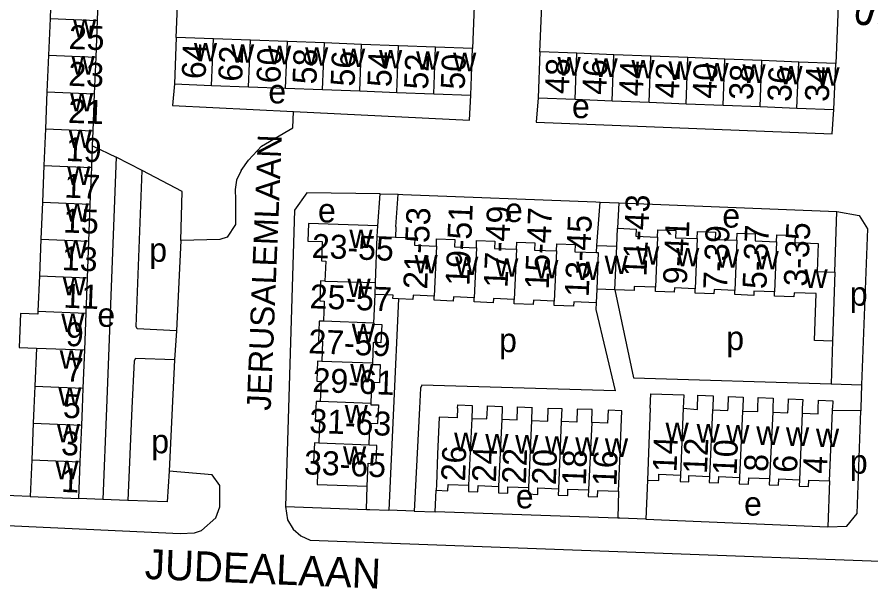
# Model space of a CAD drawing. Extents: x 159675 to 162108, y 386471 to 388472.
# Drawn here: x 161483.1 to 161625.6, y 387220.7 to 387315.3 of the extents above; entities that cross this region are included whole.
import ezdxf

# ---------------------------------------------------------------- set-up
doc = ezdxf.new("R2010")
doc.units = 0
for name, color, linetype in [('BLT_Basislijn', 7, 'Continuous'), ('BLT_Bebouwing', 7, 'Continuous'), ('BLT_Centroide', 7, 'Continuous'), ('BLT_Huisnummer', 7, 'Continuous'), ('BLT_Huisnummer_ tussenligend', 7, 'Continuous'), ('BLT_Huisnummer_reeks', 7, 'Continuous'), ('BLT_Onderdoorgang_en_onderverdeling', 7, 'Continuous'), ('BLT_Onderverdeling_panden', 7, 'Continuous'), ('BLT_Straatnaam', 7, 'Continuous'), ('BLT_Straatnaam_verkleind', 7, 'Continuous')]:
    doc.layers.add(name, color=color, linetype=linetype)

msp = doc.modelspace()

# ---------------------------------------------------------------- linework, layer by layer
at = {"layer": 'BLT_Basislijn'}
for p, q in [((161509.67, 387311.89), (161510.15, 387324.8)), ((161559.58, 387322.6), (161559.09, 387310.04)), ((161570.35, 387309.51), (161570.84, 387322.24)), ((161620.23, 387320.2), (161619.72, 387307.54)), ((161495.7, 387293.78), (161499.65, 387291.89)), ((161499.65, 387291.89), (161498.02, 387250)), ((161503.99, 387289.7), (161499.65, 387291.89)), ((161543.27, 387280.42), (161543.71, 387285.81)), ((161543.71, 387285.81), (161546.67, 387285.72)), ((161546.3, 387280.3), (161546.67, 387285.72)), ((161579.85, 387277.18), (161580.4, 387284.4)), ((161580.4, 387284.4), (161583.52, 387284.28)), ((161583.52, 387284.28), (161583.29, 387280.03)), ((161583.52, 387284.28), (161619.87, 387282.84)), ((161619.54, 387272.72), (161619.87, 387282.84)), ((161546.3, 387280.3), (161546.23, 387278.55)), ((161510.45, 387278.01), (161509.72, 387262.95)), ((161546.72, 387268.27), (161545.9, 387250)), ((161509.72, 387262.95), (161509.39, 387258.09)), ((161619.17, 387261.21), (161618.94, 387254.08)), ((161509.39, 387258.09), (161508.99, 387250)), ((161618.94, 387254.08), (161624.01, 387253.93)), ((161624.01, 387253.93), (161623.89, 387250)), ((161498.02, 387250), (161497.42, 387234.78)), ((161502.27, 387250), (161501.56, 387234.62)), ((161508.99, 387250), (161508.47, 387239.5)), ((161528.41, 387250), (161527.91, 387233.59)), ((161545.9, 387250), (161545.13, 387232.97)), ((161550.26, 387250), (161549.36, 387232.83)), ((161623.88, 387249.57), (161619.14, 387249.65)), ((161623.89, 387250), (161623.88, 387249.57)), ((161588.29, 387238.02), (161588.03, 387231.49)), ((161618.68, 387237.87), (161618.37, 387230.19)), ((161541.43, 387233.1), (161541.54, 387236.98)), ((161552.86, 387232.71), (161553.02, 387236.32)), ((161485.3, 387235.26), (161473.27, 387235.78)), ((161497.42, 387234.78), (161493.41, 387234.93)), ((161583.47, 387236.17), (161583.37, 387231.68)), ((161501.56, 387234.62), (161497.42, 387234.78)), ((161527.91, 387233.59), (161541.43, 387233.1)), ((161549.36, 387232.83), (161545.13, 387232.97)), ((161549.36, 387232.83), (161552.86, 387232.71)), ((161583.37, 387231.68), (161552.86, 387232.71)), ((161588.03, 387231.49), (161618.37, 387230.19))]:
    msp.add_line(p, q, dxfattribs=at)
for points in [[(161509.38, 387304.12), (161509.03, 387300.52), (161529.2, 387299.52)], [(161529.2, 387299.52), (161558.61, 387298.06), (161558.8, 387302.25)], [(161570.05, 387301.81), (161569.73, 387297.74), (161619.1, 387295.81), (161619.41, 387299.85)], [(161520.47, 387289.7), (161521.73, 387291.4), (161523.89, 387293.76), (161529.09, 387296.81), (161529.2, 387299.52)], [(161509.72, 387262.95), (161503.12, 387263.25), (161502.99, 387263.62), (161503.99, 387289.7)], [(161510.45, 387278.01), (161510.64, 387286.16), (161503.99, 387289.7)], [(161520.47, 387289.7), (161519.69, 387288.07), (161519.49, 387286.51), (161519.52, 387284.82), (161519.57, 387280.69), (161518.14, 387278.53), (161516.96, 387278.16), (161510.45, 387278.01)], [(161543.71, 387285.81), (161531.44, 387285.94), (161529.41, 387283.05), (161528.41, 387250)], [(161546.67, 387285.72), (161547.47, 387285.69), (161579.65, 387284.43), (161580.4, 387284.4)], [(161619.87, 387282.84), (161623.59, 387282.17), (161624.99, 387279.93), (161624.01, 387253.93)], [(161582.86, 387269.76), (161585.96, 387255.09), (161618.94, 387254.08)], [(161579.73, 387267.58), (161579.68, 387266.5), (161582.9, 387252.91), (161550.66, 387253.83), (161550.43, 387253.33), (161550.26, 387250)], [(161509.39, 387258.09), (161502.88, 387258.29), (161502.64, 387257.94), (161502.27, 387250)], [(161618.37, 387230.19), (161621.57, 387230.31), (161623.29, 387232.41), (161623.88, 387249.57)], [(161423.81, 387236.03), (161425.85, 387233.74), (161426.74, 387233.29), (161429.71, 387232.82), (161510.3, 387229.1), (161512.68, 387229.19), (161513.9, 387229.58), (161516.29, 387231.74), (161516.94, 387233.55), (161516.96, 387237.09), (161515.67, 387238.87), (161508.47, 387239.5)], [(161508.47, 387239.5), (161508.16, 387234.37), (161501.56, 387234.62)], [(161527.91, 387233.59), (161528.24, 387231.4), (161529.19, 387229.84), (161530.47, 387228.72), (161532.02, 387228.01), (161634.68, 387224.19), (161640.03, 387222.45), (161643.68, 387219.17), (161645.58, 387219.17)], [(161541.43, 387233.1), (161541.94, 387233.08), (161545.13, 387232.97)], [(161588.03, 387231.49), (161583.68, 387231.67), (161583.37, 387231.68)]]:
    msp.add_lwpolyline(points, dxfattribs=at)
at = {"layer": 'BLT_Bebouwing'}
for p, q in [((161488.85, 387321.21), (161488.6, 387315.07)), ((161488.6, 387315.07), (161488.34, 387308.93)), ((161496.28, 387308.6), (161496.51, 387314.74)), ((161509.67, 387311.89), (161509.38, 387304.12)), ((161515.85, 387311.66), (161509.67, 387311.89)), ((161522.03, 387311.43), (161515.85, 387311.66)), ((161528.21, 387311.2), (161522.03, 387311.43)), ((161534.39, 387310.96), (161528.21, 387311.2)), ((161540.56, 387310.73), (161534.39, 387310.96)), ((161546.74, 387310.5), (161540.56, 387310.73)), ((161552.92, 387310.27), (161546.74, 387310.5)), ((161559.09, 387310.04), (161552.92, 387310.27)), ((161558.8, 387302.25), (161559.09, 387310.04)), ((161570.35, 387309.51), (161570.05, 387301.81)), ((161576.52, 387309.26), (161570.35, 387309.51)), ((161582.7, 387309.01), (161576.52, 387309.26)), ((161588.87, 387308.77), (161582.7, 387309.01)), ((161488.34, 387308.93), (161488.09, 387302.79)), ((161496.04, 387302.46), (161496.28, 387308.6)), ((161595.04, 387308.52), (161588.87, 387308.77)), ((161601.21, 387308.28), (161595.04, 387308.52)), ((161607.38, 387308.03), (161601.21, 387308.28)), ((161613.55, 387307.78), (161607.38, 387308.03)), ((161619.72, 387307.54), (161613.55, 387307.78)), ((161619.41, 387299.85), (161619.72, 387307.54)), ((161509.38, 387304.12), (161515.56, 387303.88)), ((161515.56, 387303.88), (161521.74, 387303.65)), ((161521.74, 387303.65), (161527.91, 387303.42)), ((161527.91, 387303.42), (161534.09, 387303.18)), ((161488.09, 387302.79), (161487.84, 387296.65)), ((161495.8, 387296.32), (161496.04, 387302.46)), ((161534.09, 387303.18), (161540.27, 387302.95)), ((161540.27, 387302.95), (161546.45, 387302.71)), ((161546.45, 387302.71), (161552.62, 387302.48)), ((161552.62, 387302.48), (161558.8, 387302.25)), ((161570.05, 387301.81), (161576.22, 387301.57)), ((161576.22, 387301.57), (161582.39, 387301.32)), ((161582.39, 387301.32), (161588.56, 387301.08)), ((161588.56, 387301.08), (161594.73, 387300.83)), ((161594.73, 387300.83), (161600.9, 387300.58)), ((161600.9, 387300.58), (161607.07, 387300.34)), ((161607.07, 387300.34), (161613.24, 387300.09)), ((161613.24, 387300.09), (161619.41, 387299.85)), ((161487.84, 387296.65), (161487.58, 387290.51)), ((161495.7, 387293.78), (161495.8, 387296.32)), ((161495.56, 387290.18), (161495.7, 387293.78)), ((161487.58, 387290.51), (161487.33, 387284.37)), ((161495.32, 387284.04), (161495.56, 387290.18)), ((161487.33, 387284.37), (161487.07, 387278.23)), ((161495.08, 387277.9), (161495.32, 387284.04)), ((161543.2, 387278.66), (161543.27, 387280.42)), ((161487.07, 387278.23), (161486.82, 387272.09)), ((161494.84, 387271.76), (161495.08, 387277.9)), ((161543.2, 387278.66), (161546.23, 387278.55)), ((161579.8, 387275.98), (161579.85, 387277.18)), ((161579.85, 387277.18), (161583.17, 387277.05)), ((161486.82, 387272.09), (161486.58, 387266.2)), ((161619.54, 387272.72), (161619.17, 387261.21)), ((161494.62, 387265.89), (161494.84, 387271.76)), ((161579.82, 387269.88), (161579.73, 387267.58)), ((161582.86, 387269.76), (161579.82, 387269.88)), ((161542.64, 387264.21), (161542.83, 387268.97)), ((161494.38, 387259.74), (161494.62, 387265.89)), ((161486.32, 387260.05), (161486.06, 387253.68)), ((161494.13, 387253.34), (161494.38, 387259.74)), ((161486.06, 387253.68), (161485.91, 387250)), ((161494, 387250), (161494.13, 387253.34)), ((161485.91, 387250), (161485.81, 387247.54)), ((161493.89, 387247.2), (161494, 387250)), ((161559.02, 387250), (161558.96, 387248.31)), ((161564.06, 387250), (161563.99, 387248.16)), ((161569.02, 387250), (161568.95, 387247.97)), ((161599.18, 387250), (161599.17, 387249.73)), ((161604.18, 387250), (161604.17, 387249.54)), ((161609.22, 387250), (161609.2, 387249.36)), ((161614.13, 387250), (161614.1, 387249.16)), ((161618.68, 387237.87), (161619.14, 387249.65)), ((161619.14, 387249.65), (161619.16, 387250)), ((161485.81, 387247.54), (161485.55, 387241.4)), ((161493.65, 387241.06), (161493.89, 387247.2)), ((161533.44, 387244.18), (161532.71, 387244.21)), ((161485.55, 387241.4), (161485.3, 387235.26)), ((161493.41, 387234.93), (161493.65, 387241.06)), ((161485.3, 387235.26), (161493.41, 387234.93))]:
    msp.add_line(p, q, dxfattribs=at)
for points in [[(161496.51, 387314.74), (161496.7, 387319.6), (161496.91, 387319.59), (161496.96, 387320.89)], [(161543.27, 387280.42), (161531.75, 387280.86), (161531.64, 387277.91), (161534.01, 387277.82), (161533.88, 387274.6), (161534.6, 387274.57), (161534.47, 387271.23)], [(161583.17, 387277.05), (161583.29, 387280.03)], [(161583.29, 387280.03), (161586.39, 387279.9), (161586.34, 387278.71), (161589.97, 387278.57)], [(161589.97, 387278.57), (161590.01, 387279.76), (161593.02, 387279.64), (161592.97, 387278.45), (161596.59, 387278.31)], [(161596.59, 387278.31), (161596.64, 387279.49), (161599.66, 387279.38), (161599.61, 387278.19), (161603.22, 387278.05)], [(161603.22, 387278.05), (161603.27, 387279.23), (161606.28, 387279.11), (161606.24, 387277.93), (161609.85, 387277.78)], [(161546.23, 387278.55), (161549.45, 387278.42), (161549.4, 387277.22), (161553.06, 387277.07)], [(161553.06, 387277.07), (161553.11, 387278.27), (161556.14, 387278.15), (161556.09, 387276.95), (161559.74, 387276.8)], [(161559.74, 387276.8), (161559.78, 387278), (161562.83, 387277.88), (161562.78, 387276.68), (161566.42, 387276.53)], [(161566.42, 387276.53), (161566.47, 387277.73), (161569.51, 387277.6), (161569.46, 387276.41), (161573.1, 387276.26)], [(161609.85, 387277.78), (161609.9, 387278.97), (161612.92, 387278.85), (161612.88, 387277.66), (161616.77, 387277.51), (161616.61, 387272.83), (161619.54, 387272.72)], [(161573.1, 387276.26), (161573.15, 387277.46), (161576.2, 387277.33), (161576.15, 387276.13), (161579.8, 387275.98)], [(161534.47, 387271.23), (161533.75, 387271.26), (161533.63, 387267.92), (161534.35, 387267.89), (161534.22, 387264.54)], [(161589.64, 387270.2), (161586.09, 387270.34), (161586.06, 387269.63), (161582.86, 387269.76)], [(161596.24, 387269.94), (161592.78, 387270.08), (161592.75, 387269.37), (161589.61, 387269.49), (161589.64, 387270.2)], [(161602.87, 387269.68), (161599.41, 387269.81), (161599.38, 387269.11), (161596.23, 387269.23), (161596.24, 387269.94)], [(161609.5, 387269.42), (161606.05, 387269.55), (161606.02, 387268.84), (161602.86, 387268.97), (161602.87, 387269.68)], [(161619.17, 387261.21), (161616.14, 387261.31), (161616.44, 387269.14), (161612.77, 387269.29), (161612.74, 387268.58), (161609.5, 387268.71), (161609.5, 387269.42)], [(161546.72, 387268.27), (161545.8, 387268.31), (161545.83, 387268.85), (161542.83, 387268.97)], [(161552.71, 387268.73), (161549.17, 387268.88), (161549.15, 387268.17), (161546.72, 387268.27)], [(161559.38, 387268.45), (161555.9, 387268.6), (161555.87, 387267.89), (161552.69, 387268.02), (161552.71, 387268.73)], [(161566.06, 387268.16), (161562.58, 387268.31), (161562.55, 387267.6), (161559.37, 387267.74), (161559.38, 387268.45)], [(161572.75, 387267.88), (161569.27, 387268.03), (161569.24, 387267.32), (161566.05, 387267.45), (161566.06, 387268.16)], [(161579.73, 387267.58), (161575.99, 387267.74), (161575.96, 387267.03), (161572.75, 387267.17), (161572.75, 387267.88)], [(161486.58, 387266.2), (161486.56, 387265.69), (161483.65, 387265.81), (161483.43, 387260.16), (161486.32, 387260.05)], [(161534.22, 387264.54), (161533.5, 387264.56), (161533.37, 387261.21), (161534.09, 387261.18), (161533.96, 387257.83)], [(161542.64, 387264.21), (161542.64, 387264.05), (161543.94, 387264), (161543.82, 387260.94), (161542.53, 387260.99), (161542.4, 387257.5)], [(161533.96, 387257.83), (161533.24, 387257.85), (161533.11, 387254.51), (161533.83, 387254.48), (161533.7, 387251.12)], [(161542.4, 387257.5), (161542.39, 387257.33), (161543.67, 387257.29), (161543.55, 387254.25), (161542.25, 387254.3), (161542.12, 387250.8)], [(161588.76, 387250), (161588.86, 387252.39), (161594.35, 387252.24), (161594.26, 387250)], [(161596.64, 387250), (161596.72, 387252.16), (161599.26, 387252.05), (161599.18, 387250)], [(161533.7, 387251.12), (161532.98, 387251.15), (161532.94, 387250)], [(161542.12, 387250.8), (161542.11, 387250.6), (161543.41, 387250.55), (161543.39, 387250)], [(161601.73, 387250), (161601.8, 387251.94), (161604.26, 387251.85), (161604.18, 387250)], [(161606.72, 387250), (161606.79, 387251.77), (161609.29, 387251.67), (161609.22, 387250)], [(161611.77, 387250), (161611.83, 387251.56), (161614.19, 387251.46), (161614.13, 387250)], [(161616.8, 387250), (161616.85, 387251.35), (161619.21, 387251.26), (161619.16, 387250)], [(161532.94, 387250), (161532.86, 387247.86), (161533.58, 387247.83), (161533.44, 387244.18)], [(161541.84, 387243.86), (161541.98, 387247.52), (161543.29, 387247.47), (161543.39, 387250)], [(161556.61, 387250), (161556.54, 387248.4), (161553.51, 387248.52), (161553.28, 387242.33), (161553.08, 387237.22), (161553.02, 387236.32)], [(161556.61, 387250), (161556.63, 387250.55), (161559.04, 387250.46), (161559.02, 387250)], [(161558.96, 387248.31), (161561.51, 387248.21), (161561.58, 387250)], [(161561.58, 387250), (161561.59, 387250.39), (161564.07, 387250.3), (161564.06, 387250)], [(161563.99, 387248.16), (161566.53, 387248.06), (161566.61, 387250)], [(161566.61, 387250), (161566.61, 387250.22), (161569.03, 387250.12), (161569.02, 387250)], [(161568.95, 387247.97), (161571.66, 387247.87), (161571.74, 387250)], [(161571.74, 387250), (161574, 387249.96), (161573.91, 387247.79)], [(161579.01, 387247.61), (161579.09, 387249.78), (161576.57, 387249.87), (161576.48, 387247.69), (161573.91, 387247.79)], [(161583.47, 387236.17), (161583.66, 387241.16), (161583.99, 387249.59), (161581.72, 387249.68), (161581.64, 387247.51), (161579.01, 387247.61)], [(161588.76, 387250), (161588.53, 387244.07), (161588.29, 387238.02)], [(161594.26, 387250), (161596.63, 387249.82), (161596.64, 387250)], [(161599.17, 387249.73), (161601.71, 387249.63), (161601.73, 387250)], [(161604.17, 387249.54), (161606.7, 387249.44), (161606.72, 387250)], [(161609.2, 387249.36), (161611.74, 387249.26), (161611.77, 387250)], [(161614.1, 387249.16), (161616.76, 387249.06), (161616.8, 387250)], [(161532.71, 387244.21), (161532.59, 387241.06), (161533.31, 387241.03), (161533.17, 387237.3), (161541.54, 387236.98)], [(161541.54, 387236.98), (161541.69, 387240.85), (161543.03, 387240.8), (161543.14, 387243.81), (161541.84, 387243.86)], [(161588.29, 387238.02), (161590.17, 387237.95), (161590.21, 387239.01), (161593.79, 387238.86)], [(161593.79, 387238.86), (161593.75, 387237.8), (161595.18, 387237.74), (161595.22, 387238.8), (161598.65, 387238.62)], [(161598.65, 387238.62), (161598.61, 387237.6), (161600.17, 387237.54), (161600.21, 387238.6), (161603.65, 387238.46)], [(161603.65, 387238.46), (161603.61, 387237.4), (161605.17, 387237.34), (161605.21, 387238.4), (161608.65, 387238.26)], [(161608.65, 387238.26), (161608.61, 387237.2), (161610.18, 387237.14), (161610.23, 387238.2), (161613.64, 387238.06)], [(161613.64, 387238.06), (161613.59, 387237), (161615.16, 387236.94), (161615.21, 387238), (161618.68, 387237.87)], [(161553.02, 387236.32), (161554.97, 387236.24), (161555.01, 387237.3), (161558.45, 387237.16)], [(161558.45, 387237.16), (161558.41, 387236.1), (161559.98, 387236.04), (161560.02, 387237.1), (161563.45, 387236.92)], [(161563.45, 387236.92), (161563.41, 387235.9), (161564.97, 387235.84), (161565.01, 387236.9), (161568.45, 387236.76)], [(161568.45, 387236.76), (161568.41, 387235.7), (161569.97, 387235.63), (161570.01, 387236.7), (161573.44, 387236.56)], [(161573.44, 387236.56), (161573.41, 387235.49), (161574.98, 387235.43), (161575.02, 387236.49), (161578.43, 387236.36)], [(161578.43, 387236.36), (161578.39, 387235.29), (161579.96, 387235.23), (161580, 387236.29), (161583.47, 387236.17)]]:
    msp.add_lwpolyline(points, dxfattribs=at)
at = {"layer": 'BLT_Onderdoorgang_en_onderverdeling'}
msp.add_line((161582.86, 387269.76), (161583.17, 387277.05), dxfattribs=at)
msp.add_lwpolyline([(161579.8, 387275.98), (161580.07, 387275.97), (161579.82, 387269.88)], dxfattribs=at)
at = {"layer": 'BLT_Onderverdeling_panden'}
for p, q in [((161488.6, 387315.07), (161496.51, 387314.74)), ((161515.56, 387303.88), (161515.85, 387311.66)), ((161521.74, 387303.65), (161522.03, 387311.43)), ((161527.91, 387303.42), (161528.21, 387311.2)), ((161534.09, 387303.18), (161534.39, 387310.96)), ((161540.27, 387302.95), (161540.56, 387310.73)), ((161546.45, 387302.71), (161546.74, 387310.5)), ((161552.62, 387302.48), (161552.92, 387310.27)), ((161576.22, 387301.57), (161576.52, 387309.26)), ((161582.39, 387301.32), (161582.7, 387309.01)), ((161488.34, 387308.93), (161496.28, 387308.6)), ((161588.56, 387301.08), (161588.87, 387308.77)), ((161594.73, 387300.83), (161595.04, 387308.52)), ((161600.9, 387300.58), (161601.21, 387308.28)), ((161607.07, 387300.34), (161607.38, 387308.03)), ((161613.24, 387300.09), (161613.55, 387307.78)), ((161488.09, 387302.79), (161496.04, 387302.46)), ((161487.84, 387296.65), (161495.8, 387296.32)), ((161487.58, 387290.51), (161495.56, 387290.18)), ((161487.33, 387284.37), (161495.32, 387284.04)), ((161487.07, 387278.23), (161495.08, 387277.9)), ((161542.9, 387270.98), (161543.2, 387278.66)), ((161589.97, 387278.57), (161589.64, 387270.2)), ((161596.59, 387278.31), (161596.24, 387269.94)), ((161603.22, 387278.05), (161602.87, 387269.68)), ((161609.85, 387277.78), (161609.5, 387269.42)), ((161553.06, 387277.07), (161552.71, 387268.73)), ((161559.74, 387276.8), (161559.38, 387268.45)), ((161566.42, 387276.53), (161566.06, 387268.16)), ((161573.1, 387276.26), (161572.75, 387267.88)), ((161486.82, 387272.09), (161494.84, 387271.76)), ((161534.47, 387271.23), (161542.9, 387270.98)), ((161542.83, 387268.97), (161542.9, 387270.98)), ((161486.58, 387266.2), (161494.62, 387265.89)), ((161542.64, 387264.21), (161534.22, 387264.54)), ((161486.32, 387260.05), (161494.38, 387259.74)), ((161542.4, 387257.5), (161533.96, 387257.83)), ((161486.06, 387253.68), (161494.13, 387253.34)), ((161542.12, 387250.8), (161533.7, 387251.12)), ((161594.26, 387250), (161593.79, 387238.86)), ((161599.17, 387249.73), (161598.65, 387238.62)), ((161604.17, 387249.54), (161603.65, 387238.46)), ((161609.2, 387249.36), (161608.65, 387238.26)), ((161614.1, 387249.16), (161613.64, 387238.06)), ((161558.96, 387248.31), (161558.45, 387237.16)), ((161563.99, 387248.16), (161563.45, 387236.92)), ((161568.95, 387247.97), (161568.45, 387236.76)), ((161573.91, 387247.79), (161573.44, 387236.56)), ((161485.81, 387247.54), (161493.89, 387247.2)), ((161579.01, 387247.61), (161578.43, 387236.36)), ((161541.84, 387243.86), (161533.44, 387244.18)), ((161485.55, 387241.4), (161493.65, 387241.06))]:
    msp.add_line(p, q, dxfattribs=at)

# ---------------------------------------------------------------- texts
at = {"layer": 'BLT_Centroide'}
for s, p in [('w', (161492.44, 387311.84)), ('w', (161512.61, 387307.89)), ('w', (161518.8, 387307.66)), ('w', (161524.97, 387307.42)), ('w', (161531.16, 387307.19)), ('w', (161537.33, 387306.95)), ('w', (161543.5, 387306.72)), ('w', (161549.69, 387306.48)), ('w', (161555.86, 387306.25)), ('w', (161492.18, 387305.69)), ('w', (161573.28, 387305.53)), ('w', (161579.45, 387305.3)), ('w', (161585.62, 387305.05)), ('w', (161591.8, 387304.8)), ('w', (161597.97, 387304.55)), ('w', (161604.14, 387304.31)), ('w', (161610.31, 387304.06)), ('w', (161616.48, 387303.81)), ('e', (161525.03, 387300.88)), ('w', (161491.94, 387299.56)), ('e', (161575.69, 387298.42)), ('w', (161491.7, 387293.41)), ('w', (161491.45, 387287.28)), ('w', (161491.2, 387281.12)), ('e', (161533.31, 387281.01)), ('e', (161564.52, 387281.08)), ('e', (161600.78, 387280.15)), ('w', (161538.55, 387276.72)), ('w', (161490.95, 387275)), ('p', (161505.15, 387274.44)), ('w', (161586.41, 387273.98)), ('w', (161593.08, 387273.7)), ('w', (161599.7, 387273.45)), ('w', (161606.34, 387273.19)), ('w', (161549.42, 387272.5)), ('w', (161556.2, 387272.22)), ('w', (161562.88, 387271.95)), ('w', (161581.14, 387272.4)), ('w', (161569.56, 387271.67)), ('w', (161576.39, 387271.38)), ('w', (161614.49, 387270.09)), ('w', (161490.71, 387268.84)), ('w', (161538.23, 387268.56)), ('p', (161622.06, 387267.12)), ('e', (161496.5, 387263.59)), ('w', (161490.47, 387262.72)), ('w', (161538.95, 387261.03)), ('p', (161563.53, 387259.37)), ('p', (161601.44, 387259.71)), ('w', (161490.21, 387256.59)), ('w', (161538.7, 387254.31)), ('w', (161489.97, 387250.44)), ('w', (161537.77, 387247.5)), ('w', (161489.73, 387244.31)), ('w', (161591.31, 387244.5)), ('w', (161596.5, 387244.28)), ('w', (161601.44, 387244.11)), ('w', (161606.45, 387243.89)), ('w', (161611.41, 387243.72)), ('w', (161616.41, 387243.52)), ('p', (161505.49, 387242.49)), ('w', (161556.03, 387242.83)), ('w', (161561.23, 387242.62)), ('w', (161566.22, 387242.45)), ('w', (161571.2, 387242.27)), ('w', (161576.25, 387242.06)), ('w', (161581.19, 387241.89)), ('w', (161537.49, 387240.59)), ('p', (161622.06, 387239.09)), ('w', (161489.48, 387238.16)), ('e', (161566.32, 387233.3)), ('e', (161604.41, 387232.08))]:
    msp.add_text(s, height=4, dxfattribs=at).set_placement(p)
at = {"layer": 'BLT_Huisnummer'}
for s, rotation, p in [('64', 87.846, (161514.55, 387304.88)), ('58', 87.846, (161533.04, 387304.01)), ('54', 87.846, (161545.54, 387303.55)), ('50', 87.846, (161557.78, 387303.13)), ('48', 87.7216, (161575.17, 387302.41)), ('42', 87.7216, (161593.51, 387301.68)), ('38', 87.7216, (161605.88, 387301.39)), ('34', 87.7216, (161618.54, 387301.09)), ('21', 357.6987, (161491.56, 387297.65)), ('17', 357.6987, (161490.93, 387285.17)), ('13', 357.6987, (161490.52, 387273.07)), ('9', 357.6987, (161491.16, 387260.41)), ('5', 357.6987, (161490.7, 387248.42)), ('14', 87.7292, (161593.14, 387239.27)), ('26', 87.7996, (161557.85, 387237.74)), ('20', 87.7996, (161572.99, 387237.16)), ('16', 87.7996, (161583.11, 387236.95)), ('8', 87.7292, (161608.38, 387239.34)), ('4', 87.7292, (161618.23, 387239.01)), ('1', 357.6987, (161490.42, 387236.04))]:
    msp.add_text(s, height=4, rotation=rotation, dxfattribs=at).set_placement(p)
at = {"layer": 'BLT_Huisnummer_ tussenligend'}
for s, rotation, p in [('25', 357.6987, (161491.67, 387309.98)), ('62', 87.846, (161520.65, 387304.45)), ('60', 87.846, (161527.03, 387304.17)), ('56', 87.846, (161539.41, 387303.65)), ('23', 357.6987, (161491.59, 387303.84)), ('52', 87.846, (161551.66, 387303.14)), ('46', 87.7216, (161581.41, 387302.26)), ('44', 87.7216, (161587.53, 387302)), ('40', 87.7216, (161599.78, 387301.61)), ('36', 87.7216, (161612.29, 387301.09)), ('19', 357.6987, (161491.18, 387291.28)), ('15', 357.6987, (161490.72, 387279.35)), ('11', 357.6987, (161490.77, 387266.8)), ('7', 357.6987, (161491.12, 387254.5)), ('3', 357.6987, (161490.4, 387242.2)), ('12', 87.7292, (161598.22, 387239.02)), ('10', 87.7292, (161603.16, 387238.78)), ('24', 87.7996, (161563, 387237.59)), ('22', 87.7996, (161568, 387237.31)), ('18', 87.7996, (161578, 387237.07)), ('6', 87.7292, (161613.24, 387239.18))]:
    msp.add_text(s, height=4, rotation=rotation, dxfattribs=at).set_placement(p)
at = {"layer": 'BLT_Huisnummer_reeks'}
for s, rotation, p in [('11-43', 87.5709, (161588.12, 387271.94)), ('19-51', 87.572, (161558.57, 387270.36)), ('17-49', 87.5709, (161564.94, 387270.04)), ('21-53', 87.5708, (161551.52, 387269.8)), ('15-47', 87.572, (161571.81, 387269.75)), ('13-45', 87.6816, (161578.48, 387268.51)), ('9-41', 87.572, (161594.86, 387270.6)), ('3-35', 87.572, (161615.02, 387270.26)), ('23-55', 357.7917, (161532.22, 387275.12)), ('7-39', 87.5717, (161601.57, 387269.76)), ('5-37', 87.572, (161608.13, 387269.84)), ('25-57', 357.7917, (161531.87, 387266.7)), ('27-59', 357.7799, (161531.65, 387259.19)), ('29-61', 357.7917, (161532.34, 387252.74)), ('31-63', 357.7917, (161531.8, 387245.92)), ('33-65', 357.7971, (161530.92, 387238.99))]:
    msp.add_text(s, height=4, rotation=rotation, dxfattribs=at).set_placement(p)
at = {"layer": 'BLT_Straatnaam'}
for s, rotation, p in [('SICHEMSTRAAT', 87.4317, (161628.02, 387313.19)), ('JUDEALAAN', 357.6125, (161504.35, 387221.53))]:
    msp.add_text(s, height=5, rotation=rotation, dxfattribs=at).set_placement(p)
at = {"layer": 'BLT_Straatnaam_verkleind'}
msp.add_text('JERUSALEMLAAN', height=3.9999, rotation=87.6626, dxfattribs=at).set_placement((161525.41, 387249.55))

doc.saveas('drawing.dxf')
